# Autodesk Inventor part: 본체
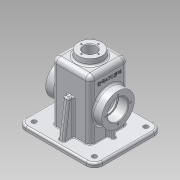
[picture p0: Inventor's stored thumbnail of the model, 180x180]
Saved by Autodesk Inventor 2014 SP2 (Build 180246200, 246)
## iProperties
Created: 2016-08
Part Number: 본체
Material: 알루미늄 6061
Document SubType Name: Modeling
Designer: user
Density: 2.71 g/cm^3
Appearance: 알루미늄 - 평지
Mass: 800.186 g
Surface Area: 912.05 cm^2
Volume: 295.272 cm^3
Author: user
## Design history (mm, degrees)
sketch "스케치1"
  geometry: L1 (-32.5, -32.5)-(32.5, -32.5); L2 (32.5, -32.5)-(32.5, 32.5); L3 (32.5, 32.5)-(-32.5, 32.5); L4 (-32.5, 32.5)-(-32.5, -32.5); L5 (-32.5, -32.5)-(32.5, 32.5); L6 (32.5, -32.5)-(-32.5, 32.5); 1 further point
  constraints: 12 end point, 2 midpoint, 2 parallel, 1 horizontal, 1 perpendicular
  dimensions: "d0" = 65 distance of L3.end L2.end; "d1" = 65 distance of L2.end L1.end
extrude "돌출1" new body sketch "스케치1" distance "d2" = 110; taper "d3" = 0 deg
feature "쉘1" dims "d4" = 5
sketch "스케치2"
  geometry: L1 (32.5, -32.5)-(-32.5, -32.5) reference; L2 (32.5, 32.5)-(32.5, -32.5) reference; L3 (-32.5, 32.5)-(32.5, 32.5) reference; L4 (-32.5, -32.5)-(-32.5, 32.5) reference; L5 (65, 57.5)-(-65, 57.5); L6 (-65, 57.5)-(-65, -57.5); L7 (-65, -57.5)-(65, -57.5); L8 (65, -57.5)-(65, 57.5); L9 (65, 57.5)-(-65, -57.5); L10 (-65, 57.5)-(65, -57.5); 1 further point
  constraints: 12 end point, 2 midpoint, 2 parallel, 1 horizontal, 1 perpendicular
  dimensions: "d5" = 130 distance of L7.end L6.end; "d6" = 115 distance of L6.end L5.end
extrude "돌출2" join sketch "스케치2" distance "d7" = 10; taper "d8" = 0 deg
sketch "스케치3"
  geometry: L1 (-65, -57.5)-(65, -57.5) reference; L2 (65, -57.5)-(65, 57.5) reference; L3 (65, 57.5)-(-65, 57.5) reference; L4 (-65, 57.5)-(-65, -57.5) reference; L5 (60, -52.5)-(-60, -52.5); L6 (-60, -52.5)-(-60, 52.5); L7 (-60, 52.5)-(60, 52.5); L8 (60, 52.5)-(60, -52.5); 1 further point
  constraints: 8 end point, 3 other
  dimensions: "d9" = 5 distance between parallel lines of L5 L1
extrude "돌출3" cut sketch "스케치3" distance "d10" = 3; taper "d11" = 0 deg
sketch "스케치4"
  geometry: C1 r 27.5 at (55, 32.5); 1 further point
  constraints: 1 centre point, 1 horizontal alignment
  dimensions: "d12" = 55 diameter of C1; "d13" = 55 distance of point (110, 32.5) C1.centre
extrude "돌출4" join sketch "스케치4" distance "d14" = 15; taper "d15" = 0 deg
sketch "스케치5"
  geometry: L1 (-27.5, 0)-(-27.5, 105) reference; L2 (-65, 10)-(65, 10) reference; L3 (-32.5, 27.5)-(-47.5, 27.5) reference; L4 (-42.5, 10)-(-42.5, 27.5); 1 further point
  constraints: 2 end point, 2 point on line, 1 perpendicular
  dimensions: "d16" = 15 distance from line of L4.start L1
feature "리브1" sketch "스케치5" dims "d17" = 1, "d18" = 6, "d19" = 0, "d20" = 0, "d21" = 1, "d22" = 1
sketch "스케치6" dims "d23" = 42
  geometry: C1 r 27.5 at (0, 0) reference; 3 further points
  constraints: 2 horizontal alignment, 1 coincident, 2 other
hole "구멍1" sketch "스케치6" at (-21, 0) diameter "d24" = 3.242; stored, may be unused: countersink angle "d28" = 90 deg, drill point angle "d30" = 118 deg; dims "d25" = 8, "d26" = 4, "d27" = 2, "d29" = 10
sketch "스케치7"
  geometry: L1 (57.5, 3)-(57.5, 10) reference; L2 (57.5, 10)-(-57.5, 10) reference; L3 (49.5, 10)-(41.068, 70); L4 (-52.5, 0)-(52.5, 0) reference; L5 (32.5, 10)-(32.5, 110) reference; L6 (41.068, 70)-(32.5, 70); 1 further point
  constraints: 4 end point, 2 point on line, 1 perpendicular
  dimensions: "d34" = 8 distance of L1.end L3.start; "d35" = 8 deg angle of L1 L3; "d36" = 70 distance from line of L4 L3.end
extrude "돌출5" join sketch "스케치7" stored distance "d37" = 10; taper "d38" = 0 deg
node "작업 평면1"
sketch "스케치8"
  geometry: C1 r 20 at (0, 0); 1 further point
  constraints: 1 centre point, 1 coincident
  dimensions: "d40" = 40 diameter of C1
extrude "돌출6" join sketch "스케치8" stored distance "d41" = 10; taper "d42" = 7 deg
hole "구멍2" diameter "d45" = 21; stored, may be unused: countersink angle "d49" = 90 deg, drill point angle "d51" = 118 deg; dims "d43" = 10, "d44" = 10, "d46" = 8, "d47" = 4, "d48" = 2, "d50" = 10
sketch "스케치9" dims "d52" = 29
  geometry: 3 further points
  constraints: 2 vertical alignment, 1 coincident, 2 other
hole "구멍3" sketch "스케치9" at (0, 14.5) diameter "d53" = 2.459; stored, may be unused: countersink angle "d57" = 90 deg, drill point angle "d59" = 118 deg; dims "d54" = 7, "d55" = 4, "d56" = 2, "d58" = 9
fillet "모깎기1" dims "d63" = 14
fillet "모깎기2" dims "d64" = 9
fillet "모깎기3" dims "d65" = 8
fillet "모깎기4" dims "d66" = 8
fillet "모깎기5" dims "d67" = 3
fillet "모깎기6" dims "d68" = 3
fillet "모깎기7" dims "d69" = 1
sketch "스케치11"
  geometry: L1 (-18, 4.5)-(-18, 44.5) reference; L2 (0, -8)-(91, -8) reference; 2 further points
  constraints: 1 other
  dimensions: "d73" = 32.5 distance from line of point (8, 24.5) L2; "d74" = 26 distance from line of point (8, 24.5) L1
feature "엠보싱1" sketch "스케치11" dims "d0" = 65, "d1" = 65, "d5" = 130, "d75" = 0.5, "d76" = 0
sketch "스케치12"
  geometry: L1 (0, 0)-(-51, 43.5); L2 (0, 0)-(51, 43.5); L3 (0, 0)-(-51, -43.5); L4 (0, 0)-(51, -43.5)
  constraints: 8 end point, 2 horizontal alignment, 2 vertical alignment, 1 collinear, 1 equal length
  dimensions: "d80" = 87 distance of L4.end L2.end; "d81" = 102 distance of L1.end L2.end
hole "구멍4" sketch "스케치12" at (-51, 43.5), (-51, -43.5), (51, -43.5), (51, 43.5) diameter "d82" = 8; stored, may be unused: countersink angle "d86" = 90 deg, drill point angle "d88" = 0 deg; dims "d83" = 7, "d84" = 4, "d85" = 2, "d87" = 9
hole "구멍5" diameter "d91" = 30; stored, may be unused: countersink angle "d95" = 90 deg, drill point angle "d97" = 0 deg; dims "d89" = 10, "d90" = 10, "d92" = 7, "d93" = 35, "d94" = 17, "d96" = 9
fillet "모깎기8" dims "d98" = 0.3
chamfer "모따기2" distance "d99" = 1; stored, may be unused: second distance "d100" = 2, angle "d101" = 45 deg
node "솔리드1"
pattern_circular "원형 패턴1" dims angle "d32" = 360 deg
mirror "대칭1"
mirror "대칭2"
pattern_circular "원형 패턴2" dims angle "d61" = 360 deg
mirror "대칭3"
